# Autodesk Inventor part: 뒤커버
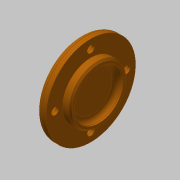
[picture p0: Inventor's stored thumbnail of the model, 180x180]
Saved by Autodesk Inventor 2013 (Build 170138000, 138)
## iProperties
Created: 2019-06
Part Number: 뒤커버
Material: 알루미늄 6061
Document SubType Name: Modeling
Designer: mduedu
Density: 2.71 g/cm^3
Mass: 40.781 g
Surface Area: 66.9578 cm^2
Volume: 15.0483 cm^3
Author: mduedu
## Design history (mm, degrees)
sketch "스케치1"
  geometry: L1 (0, 0)-(-5, 0); L2 (-5, 0)-(-5, 17.5); L3 (-5, 17.5)-(0, 17.5); L4 (0, 17.5)-(0, 0); L5 (-5, 0)-(-11, 0); L6 (-11, 0)-(-11, 27.5); L7 (-11, 27.5)-(-5, 27.5); L8 (-5, 27.5)-(-5, 0)
  constraints: 16 end point, 4 parallel, 2 horizontal, 2 perpendicular
  dimensions: "d0" = 11 distance between parallel lines of L4 L6; "d2" = 5 distance of L2.end L3.end; "d3" = 55 diameter of L7 L5; "d4" = 35 diameter of L3 L1
revolve "회전1" sketch "스케치1" stored, may be unused: angle "d5" = 90 deg
sketch "스케치2"
  geometry: C1 r 15 at (0, 0); 1 further point
  constraints: 1 centre point, 1 coincident
  dimensions: "d6" = 30 diameter of C1
extrude "돌출1" cut sketch "스케치2" distance "d7" = 4; taper "d8" = 0 deg
fillet "모깎기1" dims "d9" = 3
fillet "모깎기2" dims "d10" = 3
chamfer "모따기1" distance "d11" = 1; stored, may be unused: second distance "d12" = 2, angle "d13" = 45 deg
sketch "스케치3" dims "d14" = 44
  geometry: 3 further points
  constraints: 2 vertical alignment, 1 coincident, 2 other
hole "구멍1" sketch "스케치3" at (0, 22) diameter "d15" = 4.5; stored, may be unused: countersink angle "d19" = 90 deg, drill point angle "d21" = 118 deg; dims "d16" = 6, "d17" = 8, "d18" = 4.4, "d20" = 8
node "솔리드1"
pattern_circular "원형 패턴1" dims angle "d23" = 360 deg
